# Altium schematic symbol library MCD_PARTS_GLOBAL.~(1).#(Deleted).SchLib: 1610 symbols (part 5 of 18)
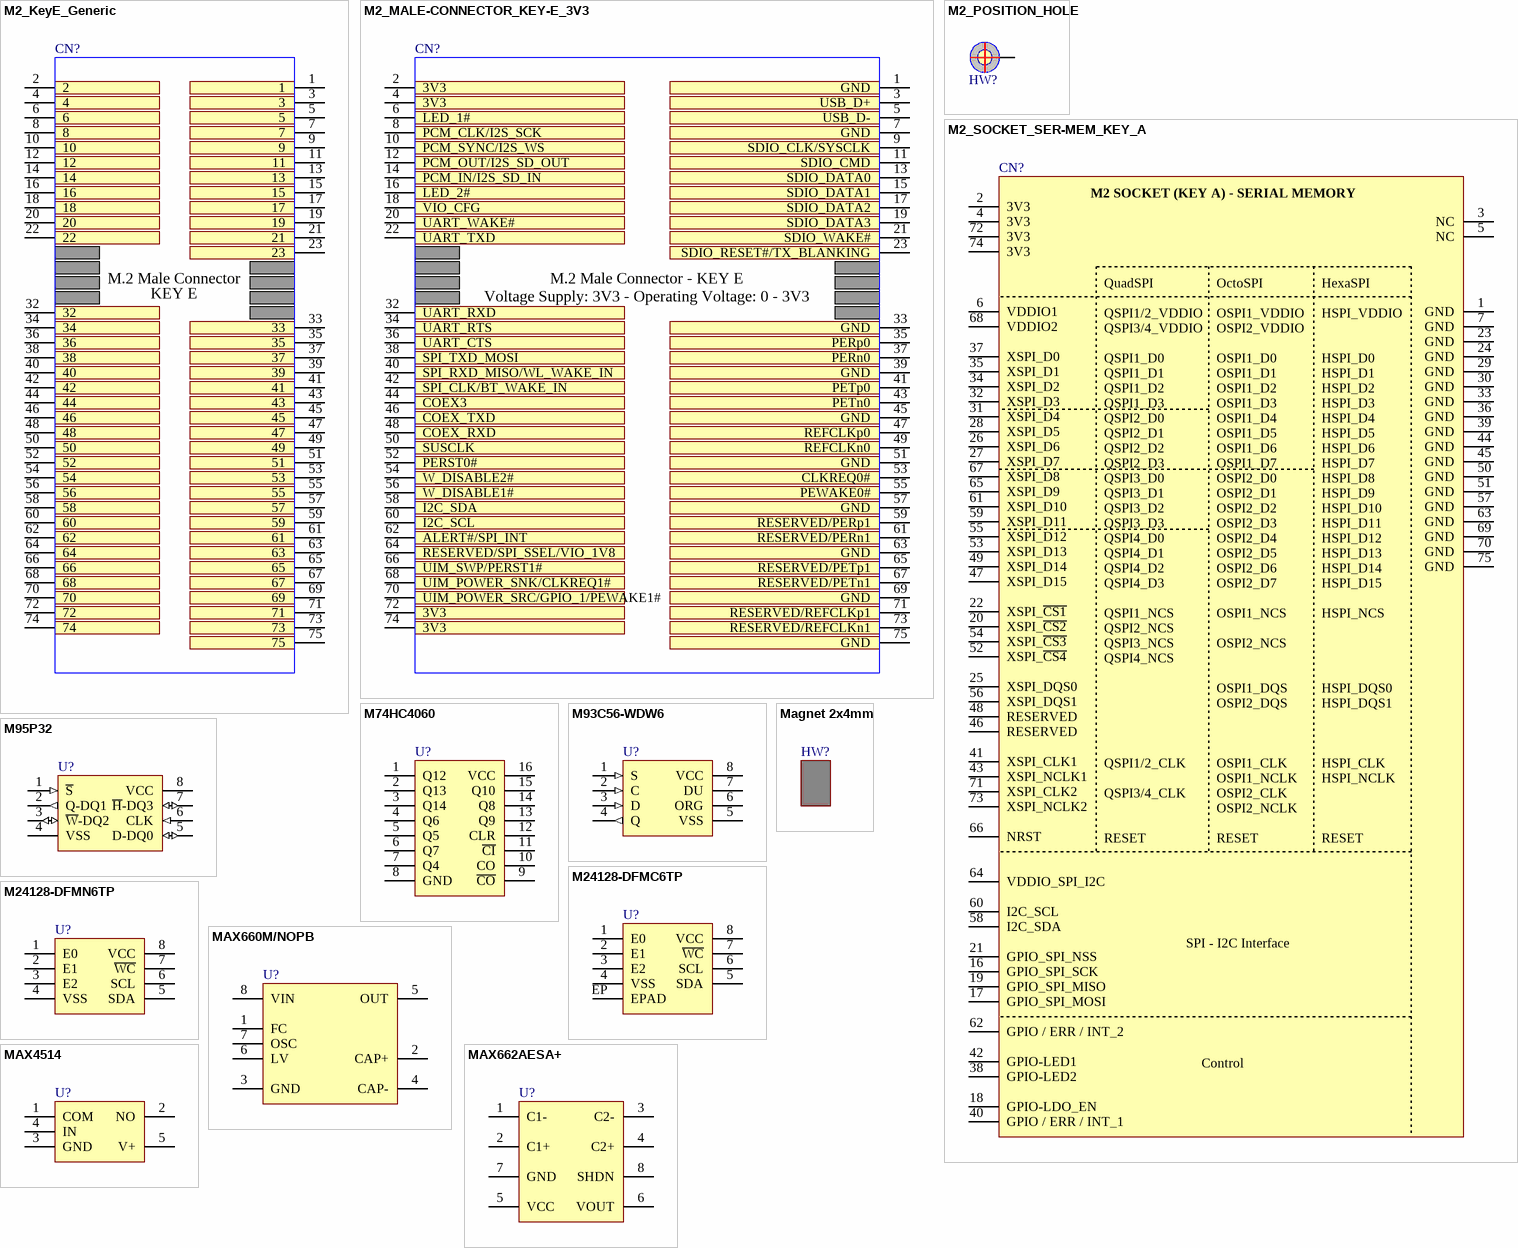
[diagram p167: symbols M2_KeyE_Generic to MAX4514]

## M2_SOCKET_SER-MEM_KEY_A
designator CN?
pins: 1 GND, 2 3V3, 3 NC, 4 3V3, 5 NC, 6 VDDIO1, 7 GND, 16 GPIO_SPI_SCK, 17 GPIO_SPI_MOSI, 18 GPIO-LDO_EN, 19 GPIO_SPI_MISO, 20 XSPI_~{CS2}, 21 GPIO_SPI_NSS, 22 XSPI_~{CS1}, 23 GND, 24 GND, 25 XSPI_DQS0, 26 XSPI_D6, 27 XSPI_D7, 28 XSPI_D5, 29 GND, 30 GND, 31 XSPI_D4, 32 XSPI_D3, 33 GND, 34 XSPI_D2, 35 XSPI_D1, 36 GND, 37 XSPI_D0, 38 GPIO-LED2, 39 GND, 40 GPIO / ERR / INT_1, 41 XSPI_CLK1, 42 GPIO-LED1, 43 XSPI_NCLK1, 44 GND, 45 GND, 46 RESERVED, 47 XSPI_D15, 48 RESERVED, 49 XSPI_D14, 50 GND, 51 GND, 52 XSPI_~{CS4}, 53 XSPI_D13, 54 XSPI_~{CS3}, 55 XSPI_D12, 56 XSPI_DQS1, 57 GND, 58 I2C_SDA, 59 XSPI_D11, 60 I2C_SCL, 61 XSPI_D10, 62 GPIO / ERR / INT_2, 63 GND, 64 VDDIO_SPI_I2C, 65 XSPI_D9, 66 NRST, 67 XSPI_D8, 68 VDDIO2, 69 GND, 70 GND, 71 XSPI_CLK2, 72 3V3, 73 XSPI_NCLK2, 74 3V3, 75 GND
1 alternate drawing of the same symbol

## M74HC4060
designator U?
pins: 1 Q12, 2 Q13, 3 Q14, 4 Q6, 5 Q5, 6 Q7, 7 Q4, 8 GND, 9 ~{CO}, 10 CO, 11 ~{CI}, 12 CLR, 13 Q9, 14 Q8, 15 Q10, 16 VCC

## M93C56-WDW6
designator U?
pins: 1 S (in), 2 C (in), 3 D (in), 4 Q (out), 5 VSS, 6 ORG, 7 DU, 8 VCC (power)

## M95P32
designator U?
pins: 1 ~{S} (in), 2 Q-DQ1 (out), 3 ~{W}-DQ2 (io), 4 VSS (power), 5 D-DQ0 (io), 6 CLK (in), 7 ~{H}-DQ3 (io), 8 VCC (power)

## M24128-DFMC6TP
designator U?
pins: 1 E0, 2 E1, 3 E2, 4 VSS, 5 SDA, 6 SCL, 7 ~{WC}, 8 VCC, EP EPAD

## M24128-DFMN6TP
designator U?
pins: 1 E0, 2 E1, 3 E2, 4 VSS, 5 SDA, 6 SCL, 7 ~{WC}, 8 VCC

## Magnet 2x4mm
designator HW?  (mechanical)

## MAX660M/NOPB
designator U?
pins: 1 FC, 2 CAP+, 3 GND, 4 CAP-, 5 OUT, 6 LV, 7 OSC, 8 VIN

## MAX662AESA+
designator U?
pins: 1 C1-, 2 C1+, 3 C2-, 4 C2+, 5 VCC, 6 VOUT, 7 GND, 8 SHDN

## MAX4514
designator U?
pins: 1 COM, 2 NO, 3 GND, 4 IN, 5 V+

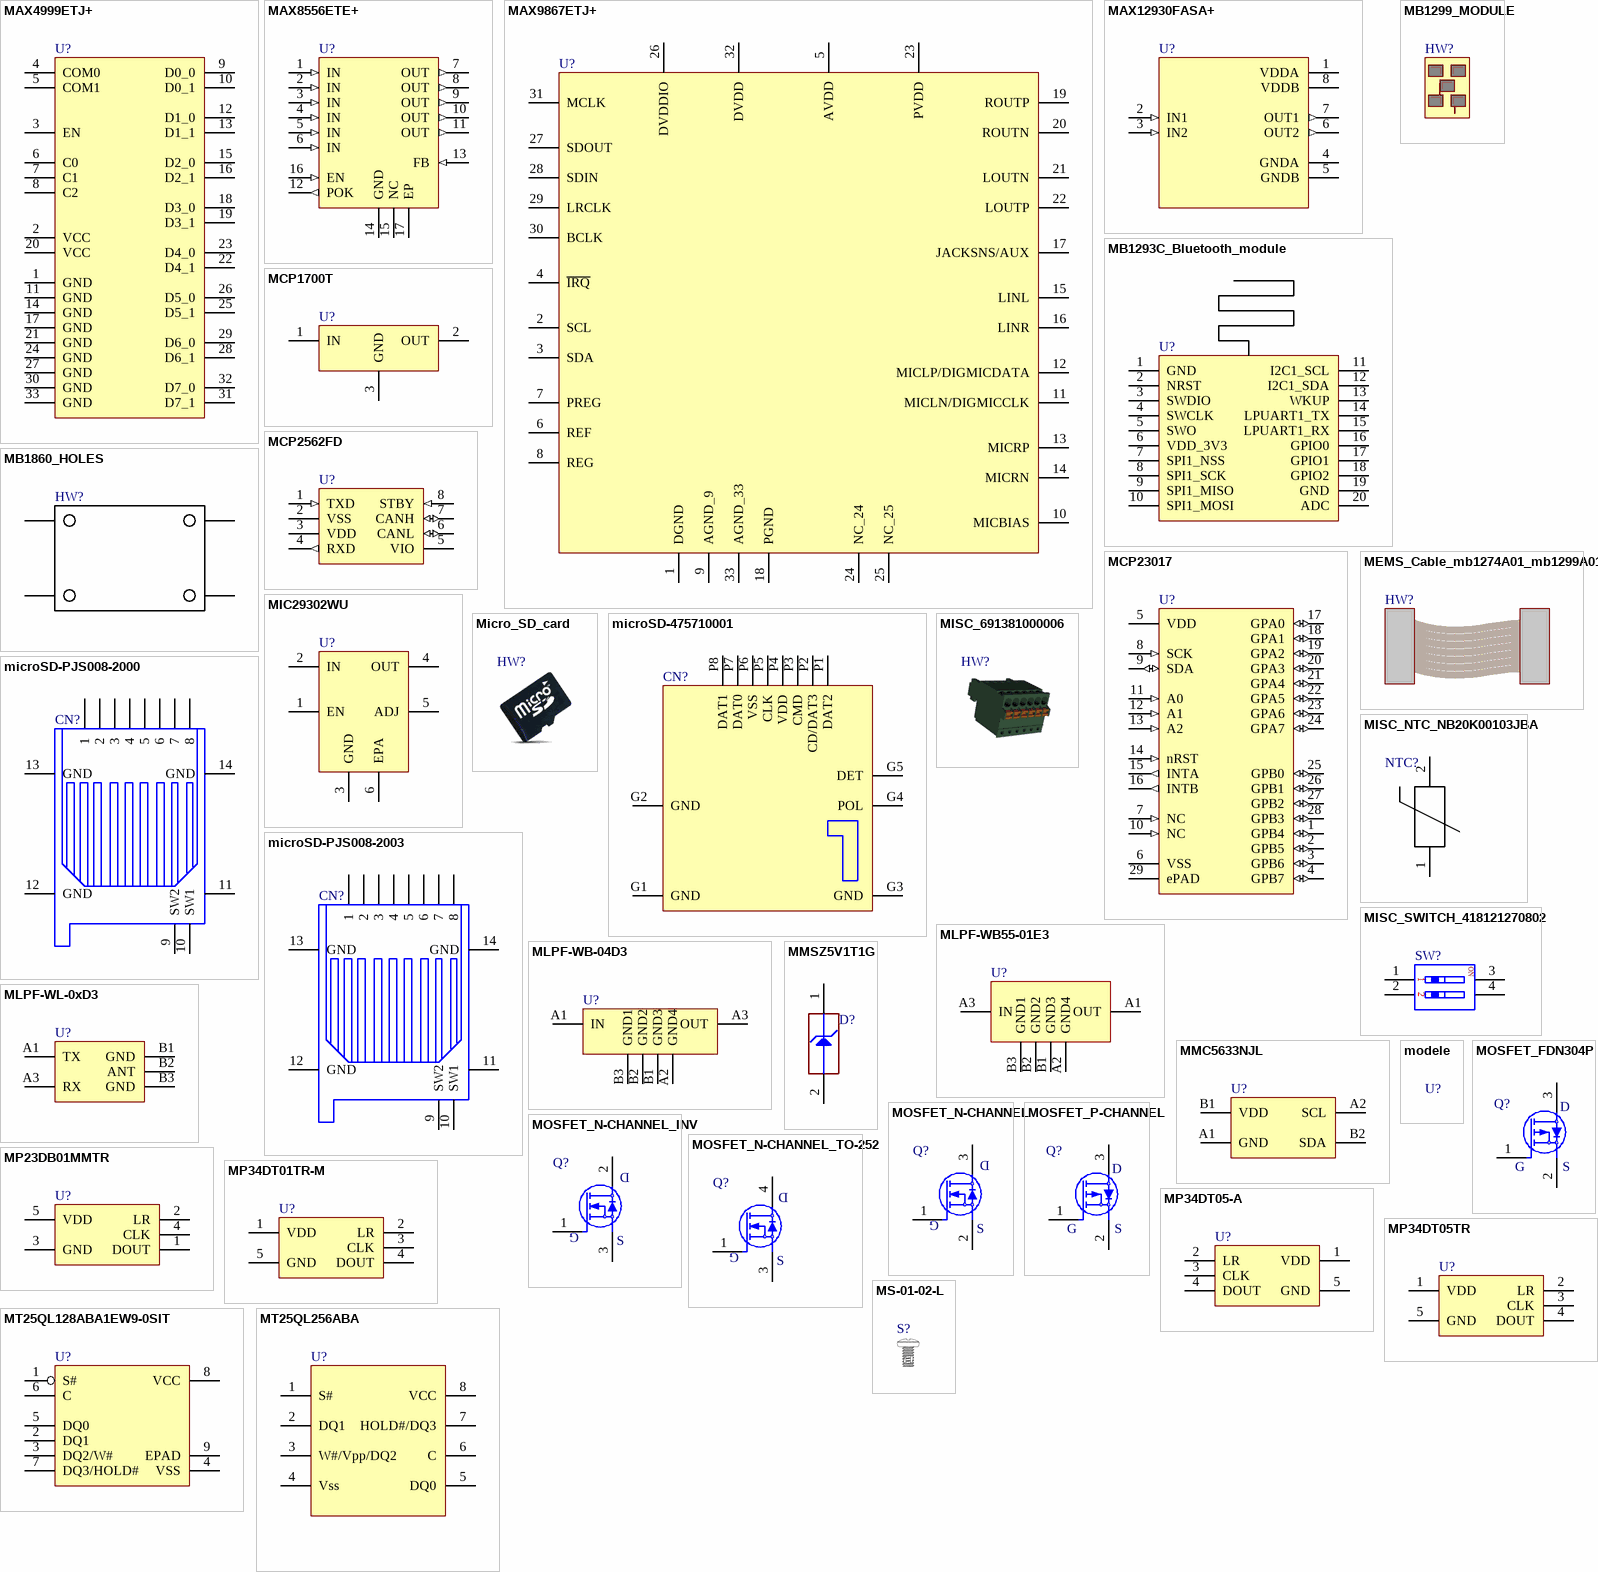
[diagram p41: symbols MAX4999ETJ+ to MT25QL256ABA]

## MAX4999ETJ+
designator U?
pins: 1 GND, 2 VCC, 3 EN, 4 COM0, 5 COM1, 6 C0, 7 C1, 8 C2, 9 D0_0, 10 D0_1, 11 GND, 12 D1_0, 13 D1_1, 14 GND, 15 D2_0, 16 D2_1, 17 GND, 18 D3_0, 19 D3_1, 20 VCC, 21 GND, 22 D4_1, 23 D4_0, 24 GND, 25 D5_1, 26 D5_0, 27 GND, 28 D6_1, 29 D6_0, 30 GND, 31 D7_1, 32 D7_0, 33 GND

## MAX8556ETE+
designator U?
pins: 1 IN (in), 2 IN (in), 3 IN (in), 4 IN (in), 5 IN (in), 6 IN (in), 7 OUT (out), 8 OUT (out), 9 OUT (out), 10 OUT (out), 11 OUT (out), 12 POK (out), 13 FB (in), 14 GND (power), 15 NC, 16 EN (in), 17 EP

## MAX9867ETJ+
designator U?
pins: 1 DGND, 2 SCL, 3 SDA, 4 ~{IRQ}, 5 AVDD, 6 REF, 7 PREG, 8 REG, 9 AGND_9, 10 MICBIAS, 11 MICLN/DIGMICCLK, 12 MICLP/DIGMICDATA, 13 MICRP, 14 MICRN, 15 LINL, 16 LINR, 17 JACKSNS/AUX, 18 PGND, 19 ROUTP, 20 ROUTN, 21 LOUTN, 22 LOUTP, 23 PVDD, 24 NC_24, 25 NC_25, 26 DVDDIO, 27 SDOUT, 28 SDIN, 29 LRCLK, 30 BCLK, 31 MCLK, 32 DVDD, 33 AGND_33

## MAX12930FASA+
designator U?
pins: 1 VDDA (power), 2 IN1 (in), 3 IN2 (in), 4 GNDA (power), 5 GNDB (power), 6 OUT2 (out), 7 OUT1 (out), 8 VDDB (power)

## MB1293C_Bluetooth_module
designator U?
pins: 1 GND, 2 NRST, 3 SWDIO, 4 SWCLK, 5 SWO, 6 VDD_3V3, 7 SPI1_NSS, 8 SPI1_SCK, 9 SPI1_MISO, 10 SPI1_MOSI, 11 I2C1_SCL, 12 I2C1_SDA, 13 WKUP, 14 LPUART1_TX, 15 LPUART1_RX, 16 GPIO0, 17 GPIO1, 18 GPIO2, 19 GND, 20 ADC

## MB1299_MODULE
designator HW?  (mechanical)

## MB1860_HOLES
designator HW?  (no BOM)
pins: GND1, GND2, GND3, GND4

## MCP1700T
designator U?
pins: 1 IN, 2 OUT, 3 GND

## MCP2562FD
designator U?
pins: 1 TXD (in), 2 VSS (power), 3 VDD (power), 4 RXD (out), 5 VIO (power), 6 CANL (io), 7 CANH (io), 8 STBY (in)

## MCP23017
designator U?
pins: 1 GPB4 (io), 2 GPB5 (io), 3 GPB6 (io), 4 GPB7 (io), 5 VDD (power), 6 VSS (power), 7 NC (in), 8 SCK (in), 9 SDA (io), 10 NC (in), 11 A0 (in), 12 A1 (in), 13 A2 (in), 14 nRST (in), 15 INTA (out), 16 INTB (out), 17 GPA0 (io), 18 GPA1 (io), 19 GPA2 (io), 20 GPA3 (io), 21 GPA4 (io), 22 GPA5 (io), 23 GPA6 (io), 24 GPA7 (io), 25 GPB0 (io), 26 GPB1 (io), 27 GPB2 (io), 28 GPB3 (io), 29 ePAD (power)

## MEMS_Cable_mb1274A01_mb1299A01
designator HW?  (mechanical)

## MIC29302WU
designator U?
pins: 1 EN, 2 IN, 3 GND, 4 OUT, 5 ADJ, 6 EPA

## Micro_SD_card
designator HW?  (mechanical)

## microSD-475710001
designator CN?
pins: G1 GND, G2 GND, G3 GND, G4 POL, G5 DET, P1 DAT2, P2 CD/DAT3, P3 CMD, P4 VDD, P5 CLK, P6 VSS, P7 DAT0, P8 DAT1

## microSD-PJS008-2000
designator CN?
pins: 1, 2, 3, 4, 5, 6, 7, 8, 9 SW2, 10 SW1, 11 GND, 12 GND, 13 GND, 14 GND

## microSD-PJS008-2003
designator CN?
pins: 1, 2, 3, 4, 5, 6, 7, 8, 9 SW2, 10 SW1, 11 GND, 12 GND, 13 GND, 14 GND
1 alternate drawing of the same symbol

## MISC_691381000006
designator HW?

## MISC_NTC_NB20K00103JBA
designator NTC?
pins: 1, 2

## MISC_SWITCH_418121270802
designator SW?
pins: 1, 2, 3, 4

## MLPF-WB55-01E3
designator U?
pins: A1 OUT, A2 GND4, A3 IN, B1 GND3, B2 GND2, B3 GND1

## MLPF-WB-04D3
designator U?
pins: A1 IN, A2 GND4, A3 OUT, B1 GND3, B2 GND2, B3 GND1

## MLPF-WL-0xD3
designator U?
pins: A1 TX, A3 RX, B1 GND, B2 ANT, B3 GND

## MMC5633NJL
designator U?
pins: A1 GND, A2 SCL, B1 VDD, B2 SDA

## MMSZ5V1T1G
designator D?
pins: 1 K, 2 A

## modele
designator U?

## MOSFET_FDN304P
designator Q?
pins: 1 G, 2 S, 3 D

## MOSFET_N-CHANNEL
designator Q?
pins: 1 G, 2 S, 3 D

## MOSFET_N-CHANNEL_INV
designator Q?
pins: 1 G, 2 D, 3 S

## MOSFET_N-CHANNEL_TO-252
designator Q?
pins: 1 G, 3 S, 4 D

## MOSFET_P-CHANNEL
designator Q?
pins: 1 G, 2 S, 3 D

## MP23DB01MMTR
designator U?
pins: 1 DOUT, 2 LR, 3 GND, 4 CLK, 5 VDD

## MP34DT01TR-M
designator U?
pins: 1 VDD, 2 LR, 3 CLK, 4 DOUT, 5 GND

## MP34DT05-A
designator U?
pins: 1 VDD, 2 LR, 3 CLK, 4 DOUT, 5 GND

## MP34DT05TR
designator U?
pins: 1 VDD, 2 LR, 3 CLK, 4 DOUT, 5 GND

## MS-01-02-L
designator S?  (mechanical)

## MT25QL128ABA1EW9-0SIT
designator U?
pins: 1 S#, 2 DQ1, 3 DQ2/W#, 4 VSS, 5 DQ0, 6 C, 7 DQ3/HOLD#, 8 VCC, 9 EPAD

## MT25QL256ABA
designator U?
pins: 1 S#, 2 DQ1, 3 W#/Vpp/DQ2, 4 Vss, 5 DQ0, 6 C, 7 HOLD#/DQ3, 8 VCC

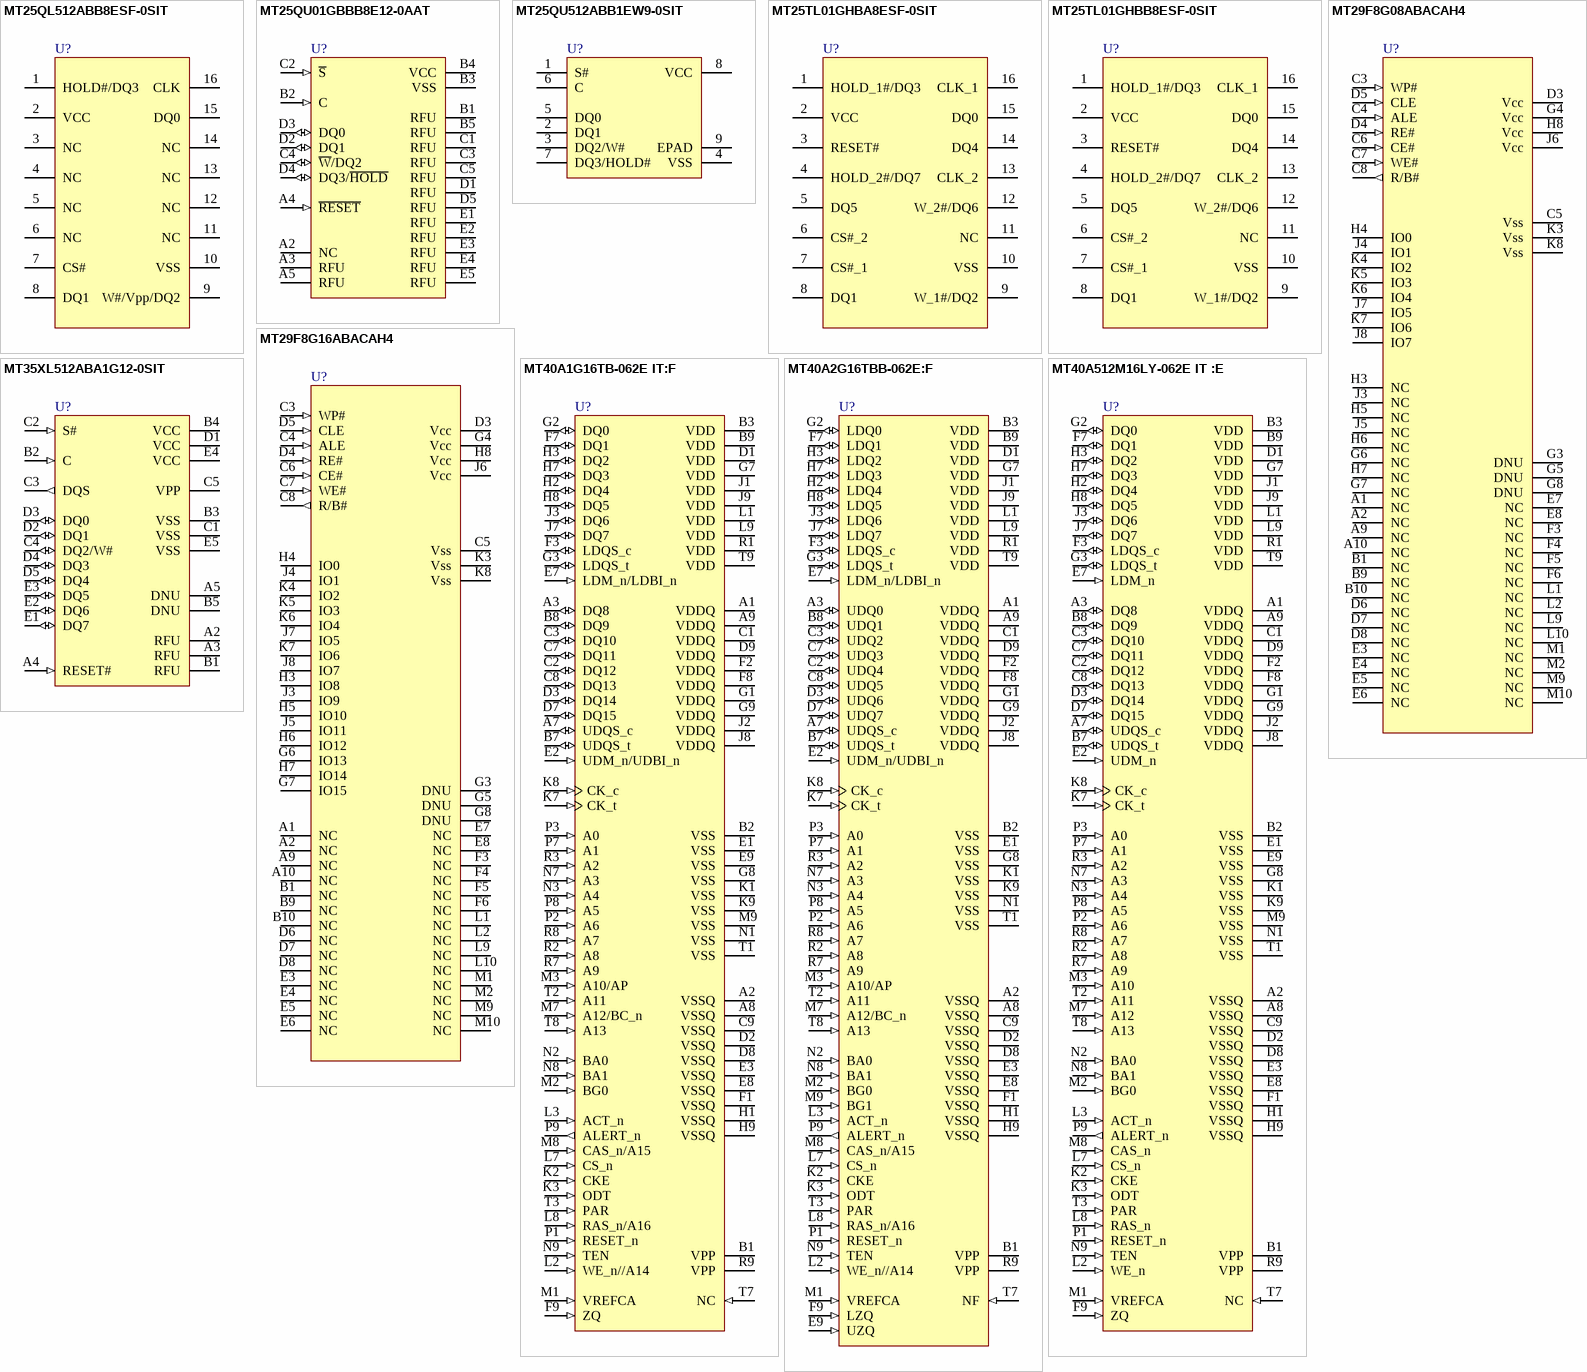
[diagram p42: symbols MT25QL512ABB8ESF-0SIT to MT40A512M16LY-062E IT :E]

## MT25QL512ABB8ESF-0SIT
designator U?
pins: 1 HOLD#/DQ3, 2 VCC, 3 NC, 4 NC, 5 NC, 6 NC, 7 CS#, 8 DQ1, 9 W#/Vpp/DQ2, 10 VSS, 11 NC, 12 NC, 13 NC, 14 NC, 15 DQ0, 16 CLK

## MT25QU01GBBB8E12-0AAT
designator U?
pins: A2 NC, A3 RFU, A4 ~{RESET} (in), A5 RFU, B1 RFU, B2 C (in), B3 VSS, B4 VCC (power), B5 RFU, C1 RFU, C2 ~{S} (in), C3 RFU, C4 ~{W}/DQ2 (io), C5 RFU, D1 RFU, D2 DQ1 (io), D3 DQ0 (io), D4 DQ3/~{HOLD} (io), D5 RFU, E1 RFU, E2 RFU, E3 RFU, E4 RFU, E5 RFU

## MT25QU512ABB1EW9-0SIT
designator U?
pins: 1 S#, 2 DQ1, 3 DQ2/W#, 4 VSS, 5 DQ0, 6 C, 7 DQ3/HOLD#, 8 VCC, 9 EPAD

## MT25TL01GHBA8ESF-0SIT
designator U?
pins: 1 HOLD_1#/DQ3, 2 VCC, 3 RESET#, 4 HOLD_2#/DQ7, 5 DQ5, 6 CS#_2, 7 CS#_1, 8 DQ1, 9 W_1#/DQ2, 10 VSS, 11 NC, 12 W_2#/DQ6, 13 CLK_2, 14 DQ4, 15 DQ0, 16 CLK_1

## MT25TL01GHBB8ESF-0SIT
designator U?
pins: 1 HOLD_1#/DQ3, 2 VCC, 3 RESET#, 4 HOLD_2#/DQ7, 5 DQ5, 6 CS#_2, 7 CS#_1, 8 DQ1, 9 W_1#/DQ2, 10 VSS, 11 NC, 12 W_2#/DQ6, 13 CLK_2, 14 DQ4, 15 DQ0, 16 CLK_1

## MT29F8G08ABACAH4
designator U?
pins: A1 NC, A2 NC, A9 NC, A10 NC, B1 NC, B9 NC, B10 NC, C3 WP# (in), C4 ALE (in), C5 Vss, C6 CE# (in), C7 WE# (in), C8 R/B# (out), D3 Vcc, D4 RE# (in), D5 CLE (in), D6 NC, D7 NC, D8 NC, E3 NC, E4 NC, E5 NC, E6 NC, E7 NC, E8 NC, F3 NC, F4 NC, F5 NC, F6 NC, G3 DNU, G4 Vcc, G5 DNU, G6 NC, G7 NC, G8 DNU, H3 NC, H4 IO0, H5 NC, H6 NC, H7 NC, H8 Vcc, J3 NC, J4 IO1, J5 NC, J6 Vcc, J7 IO5, J8 IO7, K3 Vss, K4 IO2, K5 IO3, K6 IO4, K7 IO6, K8 Vss, L1 NC, L2 NC, L9 NC, L10 NC, M1 NC, M2 NC, M9 NC, M10 NC

## MT29F8G16ABACAH4
designator U?
pins: A1 NC, A2 NC, A9 NC, A10 NC, B1 NC, B9 NC, B10 NC, C3 WP# (in), C4 ALE (in), C5 Vss, C6 CE# (in), C7 WE# (in), C8 R/B# (out), D3 Vcc, D4 RE# (in), D5 CLE (in), D6 NC, D7 NC, D8 NC, E3 NC, E4 NC, E5 NC, E6 NC, E7 NC, E8 NC, F3 NC, F4 NC, F5 NC, F6 NC, G3 DNU, G4 Vcc, G5 DNU, G6 IO13, G7 IO15, G8 DNU, H3 IO8, H4 IO0, H5 IO10, H6 IO12, H7 IO14, H8 Vcc, J3 IO9, J4 IO1, J5 IO11, J6 Vcc, J7 IO5, J8 IO7, K3 Vss, K4 IO2, K5 IO3, K6 IO4, K7 IO6, K8 Vss, L1 NC, L2 NC, L9 NC, L10 NC, M1 NC, M2 NC, M9 NC, M10 NC

## MT35XL512ABA1G12-0SIT
designator U?
pins: A2 RFU, A3 RFU, A4 RESET# (in), A5 DNU, B1 RFU, B2 C (in), B3 VSS (power), B4 VCC (power), B5 DNU, C1 VSS (power), C2 S# (in), C3 DQS (out), C4 DQ2/W# (io), C5 VPP (power), D1 VCC (power), D2 DQ1 (io), D3 DQ0 (io), D4 DQ3 (io), D5 DQ4 (io), E1 DQ7 (io), E2 DQ6 (io), E3 DQ5 (io), E4 VCC (power), E5 VSS (power)

## MT40A1G16TB-062E IT:F
designator U?
pins: A1 VDDQ (power) "DQ power supply: Isolated on the die for improved noise immunity.", A2 VSSQ (power) "DQ ground.", A3 DQ8 (io) "Data input/output: Bidirectional data bus.", A7 UDQS_c (io) "Data strobe: The data strobe is bidirectional (used for read and write data) andcomplementary (DQS and DQS#). It is edge-aligned output with read data andcentered input with write data. DQS[3:0]/DQS[3:0]# is DQS for each of (See Datasheet)", A8 VSSQ (power) "DQ ground.", A9 VDDQ (power) "DQ power supply: Isolated on the die for improved noise immunity.", B1 VPP (power) "DRAM activating power supply", B2 VSS (power) "Common ground.", B3 VDD (power) "Power supply", B7 UDQS_t (io) "Data strobe: The data strobe is bidirectional (used for read and write data) andcomplementary (DQS and DQS#). It is edge-aligned output with read data andcentered input with write data. DQS[3:0]/DQS[3:0]# is DQS for each of (See Datasheet)", B8 DQ9 (io) "Data input/output: Bidirectional data bus.", B9 VDD (power) "Power supply", C1 VDDQ (power) "DQ power supply: Isolated on the die for improved noise immunity.", C2 DQ12 (io) "Data input/output: Bidirectional data bus.", C3 DQ10 (io) "Data input/output: Bidirectional data bus.", C7 DQ11 (io) "Data input/output: Bidirectional data bus.", C8 DQ13 (io) "Data input/output: Bidirectional data bus.", C9 VSSQ (power) "DQ ground.", D1 VDD (power) "Power supply", D2 VSSQ (power) "DQ ground.", D3 DQ14 (io) "Data input/output: Bidirectional data bus.", D7 DQ15 (io) "Data input/output: Bidirectional data bus.", D8 VSSQ (power) "DQ ground.", D9 VDDQ (power) "DQ power supply: Isolated on the die for improved noise immunity.", E1 VSS (power) "Common ground.", E2 UDM_n/UDBI_n (in) "Input data mask: DM is an input mask signal for write data. Although DM ballsare input-only, the DM loading is designed to match that of DQ and DQS balls.DM[3:0] is DM for each of the four data bytes, respectively.", E3 VSSQ (power) "DQ ground.", E7 LDM_n/LDBI_n (in) "Input data mask: DM is an input mask signal for write data. Although DM ballsare input-only, the DM loading is designed to match that of DQ and DQS balls.DM[3:0] is DM for each of the four data bytes, respectively.", E8 VSSQ (power) "DQ ground.", E9 VSS (power) "Common ground.", F1 VSSQ (power) "DQ ground.", F2 VDDQ (power) "DQ power supply: Isolated on the die for improved noise immunity.", F3 LDQS_c (io) "Data strobe: The data strobe is bidirectional (used for read and write data) andcomplementary (DQS and DQS#). It is edge-aligned output with read data andcentered input with write data. DQS[3:0]/DQS[3:0]# is DQS for each of (See Datasheet)", F7 DQ1 (io) "Data input/output: Bidirectional data bus.", F8 VDDQ (power) "DQ power supply: Isolated on the die for improved noise immunity.", F9 ZQ (in) "External impedance (240 ohm): This signal is used to calibrate the device output impedance.", G1 VDDQ (power) "DQ power supply: Isolated on the die for improved noise immunity.", G2 DQ0 (io) "Data input/output: Bidirectional data bus.", G3 LDQS_t (io) "Data strobe: The data strobe is bidirectional (used for read and write data) andcomplementary (DQS and DQS#). It is edge-aligned output with read data andcentered input with write data. DQS[3:0]/DQS[3:0]# is DQS for each of (See Datasheet)", G7 VDD (power) "Power supply", G8 VSS (power) "Common ground.", G9 VDDQ (power) "DQ power supply: Isolated on the die for improved noise immunity.", H1 VSSQ (power) "DQ ground.", H2 DQ4 (io) "Data input/output: Bidirectional data bus.", H3 DQ2 (io) "Data input/output: Bidirectional data bus.", H7 DQ3 (io) "Data input/output: Bidirectional data bus.", H8 DQ5 (io) "Data input/output: Bidirectional data bus.", H9 VSSQ (power) "DQ ground.", J1 VDD (power) "Power supply", J2 VDDQ (power) "DQ power supply: Isolated on the die for improved noise immunity.", J3 DQ6 (io) "Data input/output: Bidirectional data bus.", J7 DQ7 (io) "Data input/output: Bidirectional data bus.", J8 VDDQ (power) "DQ power supply: Isolated on the die for improved noise immunity.", J9 VDD (power) "Power supply", K1 VSS (power) "Common ground.", K2 CKE (in) "Clock enable: CKE HIGH activates and CKE LOW deactivates the internal clocksignals, input buffers, and output drivers. Power-saving modes are entered andexited via CKE transitions. CKE is considered part of the command code. (See Datasheet)", K3 ODT (in) "on die termination on data, data strobe and data mask", K7 CK_t (in) "Clock: CK and CK# are differential clock inputs. All CA inputs are sampled onboth rising and falling edges of CK. CS and CKE inputs are sampled at the risingedge of CK. AC timings are referenced to clock.", K8 CK_c (in) "Clock: CK and CK# are differential clock inputs. All CA inputs are sampled onboth rising and falling edges of CK. CS and CKE inputs are sampled at the risingedge of CK. AC timings are referenced to clock.", K9 VSS (power) "Common ground.", L1 VDD (power) "Power supply", L2 WE_n//A14 (in) "Command/address inputs: Provide the command and address inputs accordingto the command truth table.", L3 ACT_n (in) "Command/address inputs: Provide the command and address inputs accordingto the command truth table.", L7 CS_n (in) "Chip select: CS# is considered part of the command code and is sampled at therising edge of CK.", L8 RAS_n/A16 (in) "Command/address inputs: Provide the command and address inputs accordingto the command truth table.", L9 VDD (power) "Power supply", M1 VREFCA (in) "Reference voltage for control, command and address pins", M2 BG0 (in) "Command/address inputs: Provide the command and address inputs accordingto the command truth table.", M3 A10/AP (in) "Command/address inputs: Provide the command and address inputs accordingto the command truth table.", M7 A12/BC_n (in) "Command/address inputs: Provide the command and address inputs accordingto the command truth table.", M8 CAS_n/A15 (in) "Command/address inputs: Provide the command and address inputs accordingto the command truth table.", M9 VSS (power) "Common ground.", N1 VSS (power) "Common ground.", N2 BA0 (in) "Command/address inputs: Provide the command and address inputs accordingto the command truth table.", N3 A4 (in) "Command/address inputs: Provide the command and address inputs accordingto the command truth table.", N7 A3 (in) "Command/address inputs: Provide the command and address inputs accordingto the command truth table.", N8 BA1 (in) "Command/address inputs: Provide the command and address inputs accordingto the command truth table.", N9 TEN (in) "Connectivity test mode", P1 RESET_n (in) "Reset active low", P2 A6 (in) "Command/address inputs: Provide the command and address inputs accordingto the command truth table.", P3 A0 (in) "Command/address inputs: Provide the command and address inputs accordingto the command truth table.", P7 A1 (in) "Command/address inputs: Provide the command and address inputs accordingto the command truth table.", P8 A5 (in) "Command/address inputs: Provide the command and address inputs accordingto the command truth table.", P9 ALERT_n (out) "Alert the controller that a specific even has occurred", R1 VDD (power) "Power supply", R2 A8 (in) "Command/address inputs: Provide the command and address inputs accordingto the command truth table.", R3 A2 (in) "Command/address inputs: Provide the command and address inputs accordingto the command truth table.", R7 A9 (in) "Command/address inputs: Provide the command and address inputs accordingto the command truth table.", R8 A7 (in) "Command/address inputs: Provide the command and address inputs accordingto the command truth table.", R9 VPP (power) "DRAM activating power supply", T1 VSS (power) "Common ground.", T2 A11 (in) "Command/address inputs: Provide the command and address inputs accordingto the command truth table.", T3 PAR (in) "Parity for command and address", T7 NC (in) "Not connected", T8 A13 (in) "Command/address inputs: Provide the command and address inputs accordingto the command truth table.", T9 VDD (power) "Power supply"

## MT40A2G16TBB-062E:F
designator U?
pins: A1 VDDQ (power) "DQ power supply: Isolated on the die for improved noise immunity.", A2 VSSQ (power) "DQ ground.", A3 UDQ0 (io) "Data input/output: Bidirectional data bus.", A7 UDQS_c (io) "Data strobe: The data strobe is bidirectional (used for read and write data) andcomplementary (DQS and DQS#). It is edge-aligned output with read data andcentered input with write data. DQS[3:0]/DQS[3:0]# is DQS for each of (See Datasheet)", A8 VSSQ (power) "DQ ground.", A9 VDDQ (power) "DQ power supply: Isolated on the die for improved noise immunity.", B1 VPP (power) "DRAM activating power supply", B2 VSS (power) "Common ground.", B3 VDD (power) "Power supply", B7 UDQS_t (io) "Data strobe: The data strobe is bidirectional (used for read and write data) andcomplementary (DQS and DQS#). It is edge-aligned output with read data andcentered input with write data. DQS[3:0]/DQS[3:0]# is DQS for each of (See Datasheet)", B8 UDQ1 (io) "Data input/output: Bidirectional data bus.", B9 VDD (power) "Power supply", C1 VDDQ (power) "DQ power supply: Isolated on the die for improved noise immunity.", C2 UDQ4 (io) "Data input/output: Bidirectional data bus.", C3 UDQ2 (io) "Data input/output: Bidirectional data bus.", C7 UDQ3 (io) "Data input/output: Bidirectional data bus.", C8 UDQ5 (io) "Data input/output: Bidirectional data bus.", C9 VSSQ (power) "DQ ground.", D1 VDD (power) "Power supply", D2 VSSQ (power) "DQ ground.", D3 UDQ6 (io) "Data input/output: Bidirectional data bus.", D7 UDQ7 (io) "Data input/output: Bidirectional data bus.", D8 VSSQ (power) "DQ ground.", D9 VDDQ (power) "DQ power supply: Isolated on the die for improved noise immunity.", E1 VSS (power) "Common ground.", E2 UDM_n/UDBI_n (in) "Input data mask: DM is an input mask signal for write data. Although DM ballsare input-only, the DM loading is designed to match that of DQ and DQS balls.DM[3:0] is DM for each of the four data bytes, respectively.", E3 VSSQ (power) "DQ ground.", E7 LDM_n/LDBI_n (in) "Input data mask: DM is an input mask signal for write data. Although DM ballsare input-only, the DM loading is designed to match that of DQ and DQS balls.DM[3:0] is DM for each of the four data bytes, respectively.", E8 VSSQ (power) "DQ ground.", E9 UZQ (in) "Common ground.", F1 VSSQ (power) "DQ ground.", F2 VDDQ (power) "DQ power supply: Isolated on the die for improved noise immunity.", F3 LDQS_c (io) "Data strobe: The data strobe is bidirectional (used for read and write data) andcomplementary (DQS and DQS#). It is edge-aligned output with read data andcentered input with write data. DQS[3:0]/DQS[3:0]# is DQS for each of (See Datasheet)", F7 LDQ1 (io) "Data input/output: Bidirectional data bus.", F8 VDDQ (power) "DQ power supply: Isolated on the die for improved noise immunity.", F9 LZQ (in) "External impedance (240 ohm): This signal is used to calibrate the device output impedance.", G1 VDDQ (power) "DQ power supply: Isolated on the die for improved noise immunity.", G2 LDQ0 (io) "Data input/output: Bidirectional data bus.", G3 LDQS_t (io) "Data strobe: The data strobe is bidirectional (used for read and write data) andcomplementary (DQS and DQS#). It is edge-aligned output with read data andcentered input with write data. DQS[3:0]/DQS[3:0]# is DQS for each of (See Datasheet)", G7 VDD (power) "Power supply", G8 VSS (power) "Common ground.", G9 VDDQ (power) "DQ power supply: Isolated on the die for improved noise immunity.", H1 VSSQ (power) "DQ ground.", H2 LDQ4 (io) "Data input/output: Bidirectional data bus.", H3 LDQ2 (io) "Data input/output: Bidirectional data bus.", H7 LDQ3 (io) "Data input/output: Bidirectional data bus.", H8 LDQ5 (io) "Data input/output: Bidirectional data bus.", H9 VSSQ (power) "DQ ground.", J1 VDD (power) "Power supply", J2 VDDQ (power) "DQ power supply: Isolated on the die for improved noise immunity.", J3 LDQ6 (io) "Data input/output: Bidirectional data bus.", J7 LDQ7 (io) "Data input/output: Bidirectional data bus.", J8 VDDQ (power) "DQ power supply: Isolated on the die for improved noise immunity.", J9 VDD (power) "Power supply", K1 VSS (power) "Common ground.", K2 CKE (in) "Clock enable: CKE HIGH activates and CKE LOW deactivates the internal clocksignals, input buffers, and output drivers. Power-saving modes are entered andexited via CKE transitions. CKE is considered part of the command code. (See Datasheet)", K3 ODT (in) "on die termination on data, data strobe and data mask", K7 CK_t (in) "Clock: CK and CK# are differential clock inputs. All CA inputs are sampled onboth rising and falling edges of CK. CS and CKE inputs are sampled at the risingedge of CK. AC timings are referenced to clock.", K8 CK_c (in) "Clock: CK and CK# are differential clock inputs. All CA inputs are sampled onboth rising and falling edges of CK. CS and CKE inputs are sampled at the risingedge of CK. AC timings are referenced to clock.", K9 VSS (power) "Common ground.", L1 VDD (power) "Power supply", L2 WE_n//A14 (in) "Command/address inputs: Provide the command and address inputs accordingto the command truth table.", L3 ACT_n (in) "Command/address inputs: Provide the command and address inputs accordingto the command truth table.", L7 CS_n (in) "Chip select: CS# is considered part of the command code and is sampled at therising edge of CK.", L8 RAS_n/A16 (in) "Command/address inputs: Provide the command and address inputs accordingto the command truth table.", L9 VDD (power) "Power supply", M1 VREFCA (in) "Reference voltage for control, command and address pins", M2 BG0 (in) "Command/address inputs: Provide the command and address inputs accordingto the command truth table.", M3 A10/AP (in) "Command/address inputs: Provide the command and address inputs accordingto the command truth table.", M7 A12/BC_n (in) "Command/address inputs: Provide the command and address inputs accordingto the command truth table.", M8 CAS_n/A15 (in) "Command/address inputs: Provide the command and address inputs accordingto the command truth table.", M9 BG1 (in) "Common ground.", N1 VSS (power) "Common ground.", N2 BA0 (in) "Command/address inputs: Provide the command and address inputs accordingto the command truth table.", N3 A4 (in) "Command/address inputs: Provide the command and address inputs accordingto the command truth table.", N7 A3 (in) "Command/address inputs: Provide the command and address inputs accordingto the command truth table.", N8 BA1 (in) "Command/address inputs: Provide the command and address inputs accordingto the command truth table.", N9 TEN (in) "Connectivity test mode", P1 RESET_n (in) "Reset active low", P2 A6 (in) "Command/address inputs: Provide the command and address inputs accordingto the command truth table.", P3 A0 (in) "Command/address inputs: Provide the command and address inputs accordingto the command truth table.", P7 A1 (in) "Command/address inputs: Provide the command and address inputs accordingto the command truth table.", P8 A5 (in) "Command/address inputs: Provide the command and address inputs accordingto the command truth table.", P9 ALERT_n (out) "Alert the controller that a specific even has occurred", R1 VDD (power) "Power supply", R2 A8 (in) "Command/address inputs: Provide the command and address inputs accordingto the command truth table.", R3 A2 (in) "Command/address inputs: Provide the command and address inputs accordingto the command truth table.", R7 A9 (in) "Command/address inputs: Provide the command and address inputs accordingto the command truth table.", R8 A7 (in) "Command/address inputs: Provide the command and address inputs accordingto the command truth table.", R9 VPP (power) "DRAM activating power supply", T1 VSS (power) "Common ground.", T2 A11 (in) "Command/address inputs: Provide the command and address inputs accordingto the command truth table.", T3 PAR (in) "Parity for command and address", T7 NF (in) "Not connected", T8 A13 (in) "Command/address inputs: Provide the command and address inputs accordingto the command truth table.", T9 VDD (power) "Power supply"

## MT40A512M16LY-062E IT :E
designator U?
pins: A1 VDDQ (power) "DQ power supply: Isolated on the die for improved noise immunity.", A2 VSSQ (power) "DQ ground.", A3 DQ8 (io) "Data input/output: Bidirectional data bus.", A7 UDQS_c (io) "Data strobe: The data strobe is bidirectional (used for read and write data) andcomplementary (DQS and DQS#). It is edge-aligned output with read data andcentered input with write data. DQS[3:0]/DQS[3:0]# is DQS for each of (See Datasheet)", A8 VSSQ (power) "DQ ground.", A9 VDDQ (power) "DQ power supply: Isolated on the die for improved noise immunity.", B1 VPP (power) "DRAM activating power supply", B2 VSS (power) "Common ground.", B3 VDD (power) "Power supply", B7 UDQS_t (io) "Data strobe: The data strobe is bidirectional (used for read and write data) andcomplementary (DQS and DQS#). It is edge-aligned output with read data andcentered input with write data. DQS[3:0]/DQS[3:0]# is DQS for each of (See Datasheet)", B8 DQ9 (io) "Data input/output: Bidirectional data bus.", B9 VDD (power) "Power supply", C1 VDDQ (power) "DQ power supply: Isolated on the die for improved noise immunity.", C2 DQ12 (io) "Data input/output: Bidirectional data bus.", C3 DQ10 (io) "Data input/output: Bidirectional data bus.", C7 DQ11 (io) "Data input/output: Bidirectional data bus.", C8 DQ13 (io) "Data input/output: Bidirectional data bus.", C9 VSSQ (power) "DQ ground.", D1 VDD (power) "Power supply", D2 VSSQ (power) "DQ ground.", D3 DQ14 (io) "Data input/output: Bidirectional data bus.", D7 DQ15 (io) "Data input/output: Bidirectional data bus.", D8 VSSQ (power) "DQ ground.", D9 VDDQ (power) "DQ power supply: Isolated on the die for improved noise immunity.", E1 VSS (power) "Common ground.", E2 UDM_n (in) "Input data mask: DM is an input mask signal for write data. Although DM ballsare input-only, the DM loading is designed to match that of DQ and DQS balls.DM[3:0] is DM for each of the four data bytes, respectively.", E3 VSSQ (power) "DQ ground.", E7 LDM_n (in) "Input data mask: DM is an input mask signal for write data. Although DM ballsare input-only, the DM loading is designed to match that of DQ and DQS balls.DM[3:0] is DM for each of the four data bytes, respectively.", E8 VSSQ (power) "DQ ground.", E9 VSS (power) "Common ground.", F1 VSSQ (power) "DQ ground.", F2 VDDQ (power) "DQ power supply: Isolated on the die for improved noise immunity.", F3 LDQS_c (io) "Data strobe: The data strobe is bidirectional (used for read and write data) andcomplementary (DQS and DQS#). It is edge-aligned output with read data andcentered input with write data. DQS[3:0]/DQS[3:0]# is DQS for each of (See Datasheet)", F7 DQ1 (io) "Data input/output: Bidirectional data bus.", F8 VDDQ (power) "DQ power supply: Isolated on the die for improved noise immunity.", F9 ZQ (in) "External impedance (240 ohm): This signal is used to calibrate the device output impedance.", G1 VDDQ (power) "DQ power supply: Isolated on the die for improved noise immunity.", G2 DQ0 (io) "Data input/output: Bidirectional data bus.", G3 LDQS_t (io) "Data strobe: The data strobe is bidirectional (used for read and write data) andcomplementary (DQS and DQS#). It is edge-aligned output with read data andcentered input with write data. DQS[3:0]/DQS[3:0]# is DQS for each of (See Datasheet)", G7 VDD (power) "Power supply", G8 VSS (power) "Common ground.", G9 VDDQ (power) "DQ power supply: Isolated on the die for improved noise immunity.", H1 VSSQ (power) "DQ ground.", H2 DQ4 (io) "Data input/output: Bidirectional data bus.", H3 DQ2 (io) "Data input/output: Bidirectional data bus.", H7 DQ3 (io) "Data input/output: Bidirectional data bus.", H8 DQ5 (io) "Data input/output: Bidirectional data bus.", H9 VSSQ (power) "DQ ground.", J1 VDD (power) "Power supply", J2 VDDQ (power) "DQ power supply: Isolated on the die for improved noise immunity.", J3 DQ6 (io) "Data input/output: Bidirectional data bus.", J7 DQ7 (io) "Data input/output: Bidirectional data bus.", J8 VDDQ (power) "DQ power supply: Isolated on the die for improved noise immunity.", J9 VDD (power) "Power supply", K1 VSS (power) "Common ground.", K2 CKE (in) "Clock enable: CKE HIGH activates and CKE LOW deactivates the internal clocksignals, input buffers, and output drivers. Power-saving modes are entered andexited via CKE transitions. CKE is considered part of the command code. (See Datasheet)", K3 ODT (in) "on die termination on data, data strobe and data mask", K7 CK_t (in) "Clock: CK and CK# are differential clock inputs. All CA inputs are sampled onboth rising and falling edges of CK. CS and CKE inputs are sampled at the risingedge of CK. AC timings are referenced to clock.", K8 CK_c (in) "Clock: CK and CK# are differential clock inputs. All CA inputs are sampled onboth rising and falling edges of CK. CS and CKE inputs are sampled at the risingedge of CK. AC timings are referenced to clock.", K9 VSS (power) "Common ground.", L1 VDD (power) "Power supply", L2 WE_n (in) "Command/address inputs: Provide the command and address inputs accordingto the command truth table.", L3 ACT_n (in) "Command/address inputs: Provide the command and address inputs accordingto the command truth table.", L7 CS_n (in) "Chip select: CS# is considered part of the command code and is sampled at therising edge of CK.", L8 RAS_n (in) "Command/address inputs: Provide the command and address inputs accordingto the command truth table.", L9 VDD (power) "Power supply", M1 VREFCA (in) "Reference voltage for control, command and address pins", M2 BG0 (in) "Command/address inputs: Provide the command and address inputs accordingto the command truth table.", M3 A10 (in) "Command/address inputs: Provide the command and address inputs accordingto the command truth table.", M7 A12 (in) "Command/address inputs: Provide the command and address inputs accordingto the command truth table.", M8 CAS_n (in) "Command/address inputs: Provide the command and address inputs accordingto the command truth table.", M9 VSS (power) "Common ground.", N1 VSS (power) "Common ground.", N2 BA0 (in) "Command/address inputs: Provide the command and address inputs accordingto the command truth table.", N3 A4 (in) "Command/address inputs: Provide the command and address inputs accordingto the command truth table.", N7 A3 (in) "Command/address inputs: Provide the command and address inputs accordingto the command truth table.", N8 BA1 (in) "Command/address inputs: Provide the command and address inputs accordingto the command truth table.", N9 TEN (in) "Connectivity test mode", P1 RESET_n (in) "Reset active low", P2 A6 (in) "Command/address inputs: Provide the command and address inputs accordingto the command truth table.", P3 A0 (in) "Command/address inputs: Provide the command and address inputs accordingto the command truth table.", P7 A1 (in) "Command/address inputs: Provide the command and address inputs accordingto the command truth table.", P8 A5 (in) "Command/address inputs: Provide the command and address inputs accordingto the command truth table.", P9 ALERT_n (out) "Alert the controller that a specific even has occurred", R1 VDD (power) "Power supply", R2 A8 (in) "Command/address inputs: Provide the command and address inputs accordingto the command truth table.", R3 A2 (in) "Command/address inputs: Provide the command and address inputs accordingto the command truth table.", R7 A9 (in) "Command/address inputs: Provide the command and address inputs accordingto the command truth table.", R8 A7 (in) "Command/address inputs: Provide the command and address inputs accordingto the command truth table.", R9 VPP (power) "DRAM activating power supply", T1 VSS (power) "Common ground.", T2 A11 (in) "Command/address inputs: Provide the command and address inputs accordingto the command truth table.", T3 PAR (in) "Parity for command and address", T7 NC (in) "Not connected", T8 A13 (in) "Command/address inputs: Provide the command and address inputs accordingto the command truth table.", T9 VDD (power) "Power supply"

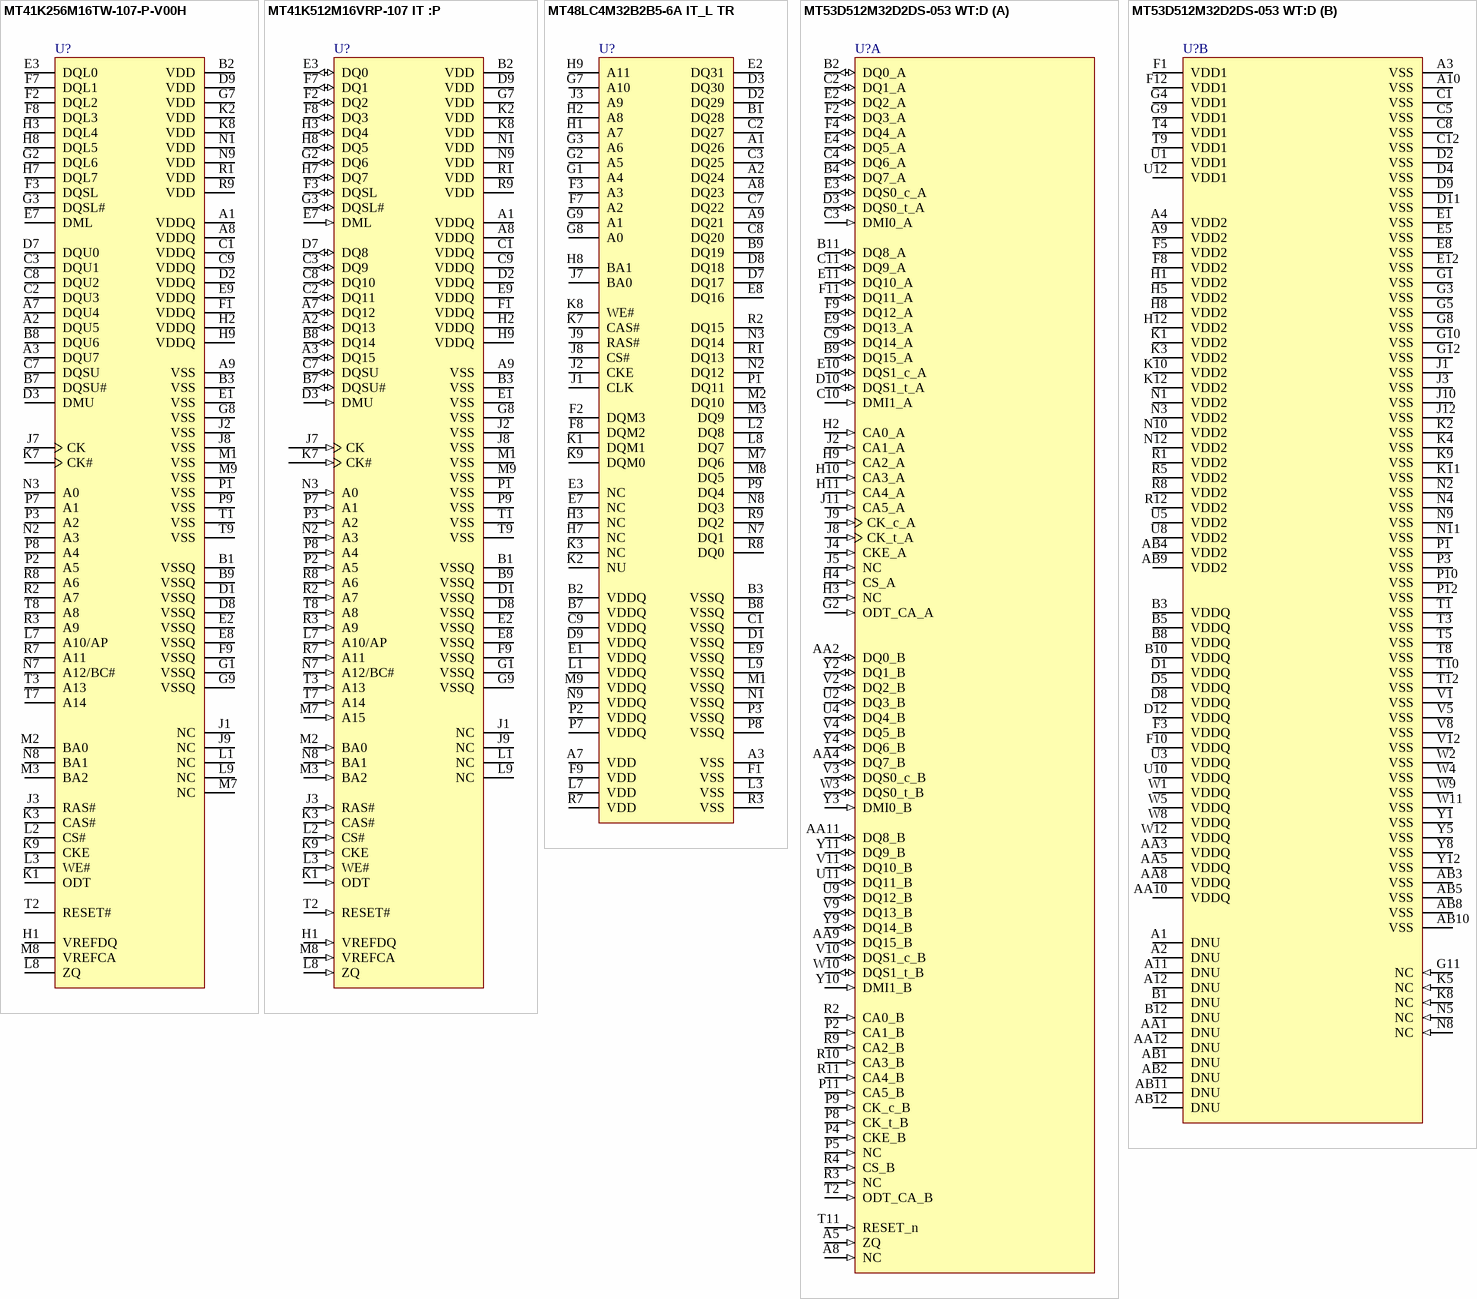
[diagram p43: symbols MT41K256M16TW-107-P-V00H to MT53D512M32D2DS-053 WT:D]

## MT41K256M16TW-107-P-V00H
designator U?
pins: A1 VDDQ "DQ Power Supply: 1.5 V +/- 0.075 V for standard voltage or 1.35V +0.1V, -0.067V for low voltage", A2 DQU5 "Data Input/ Output: Bi-directional data bus.", A3 DQU7 "Data Input/ Output: Bi-directional data bus.", A7 DQU4 "Data Input/ Output: Bi-directional data bus.", A8 VDDQ "DQ Power Supply: 1.5 V +/- 0.075 V for standard voltage or 1.35V +0.1V, -0.067V for low voltage", A9 VSS "Ground", B1 VSSQ "DQ Ground", B2 VDD "Power Supply: 1.5 V +/- 0.075 V for standard voltage or 1.35V +0.1V, -0.067V for low voltage", B3 VSS "Ground", B7 DQSU# "Data Strobe: output with read data, input with write data. Edge-aligned with read data, centered in write data. For the x16, DQSL corresponds to the data on DQL0-DQL7; DQSU corresponds to the data on DQU0-DQU7. The data strobes DQS, DQSL, and DQSU are pa", B8 DQU6 "Data Input/ Output: Bi-directional data bus.", B9 VSSQ "DQ Ground", C1 VDDQ "DQ Power Supply: 1.5 V +/- 0.075 V for standard voltage or 1.35V +0.1V, -0.067V for low voltage", C2 DQU3 "Data Input/ Output: Bi-directional data bus.", C3 DQU1 "Data Input/ Output: Bi-directional data bus.", C7 DQSU "Data Strobe: output with read data, input with write data. Edge-aligned with read data, centered in write data. For the x16, DQSL corresponds to the data on DQL0-DQL7; DQSU corresponds to the data on DQU0-DQU7. The data strobes DQS, DQSL, and DQSU are pa", C8 DQU2 "Data Input/ Output: Bi-directional data bus.", C9 VDDQ "DQ Power Supply: 1.5 V +/- 0.075 V for standard voltage or 1.35V +0.1V, -0.067V for low voltage", D1 VSSQ "DQ Ground", D2 VDDQ "DQ Power Supply: 1.5 V +/- 0.075 V for standard voltage or 1.35V +0.1V, -0.067V for low voltage", D3 DMU "Input Data Mask: DM is an input mask signal for write data. Input data is masked when DM is sampled HIGH coincident with that input data during a Write access. DM is sampled on both edges of DQS. For x8 device, the function of DM or TDQS/TDQS# is enabled", D7 DQU0 "Data Input/ Output: Bi-directional data bus.", D8 VSSQ "DQ Ground", D9 VDD "Power Supply: 1.5 V +/- 0.075 V for standard voltage or 1.35V +0.1V, -0.067V for low voltage", E1 VSS "Ground", E2 VSSQ "DQ Ground", E3 DQL0 "Data Input/ Output: Bi-directional data bus.", E7 DML "Input Data Mask: DM is an input mask signal for write data. Input data is masked when DM is sampled HIGH coincident with that input data during a Write access. DM is sampled on both edges of DQS. For x8 device, the function of DM or TDQS/TDQS# is enabled", E8 VSSQ "DQ Ground", E9 VDDQ "DQ Power Supply: 1.5 V +/- 0.075 V for standard voltage or 1.35V +0.1V, -0.067V for low voltage", F1 VDDQ "DQ Power Supply: 1.5 V +/- 0.075 V for standard voltage or 1.35V +0.1V, -0.067V for low voltage", F2 DQL2 "Data Input/ Output: Bi-directional data bus.", F3 DQSL "Data Strobe: output with read data, input with write data. Edge-aligned with read data, centered in write data. For the x16, DQSL corresponds to the data on DQL0-DQL7; DQSU corresponds to the data on DQU0-DQU7. The data strobes DQS, DQSL, and DQSU are pa", F7 DQL1 "Data Input/ Output: Bi-directional data bus.", F8 DQL3 "Data Input/ Output: Bi-directional data bus.", F9 VSSQ "DQ Ground", G1 VSSQ "DQ Ground", G2 DQL6 "Data Input/ Output: Bi-directional data bus.", G3 DQSL# "Data Strobe: output with read data, input with write data. Edge-aligned with read data, centered in write data. For the x16, DQSL corresponds to the data on DQL0-DQL7; DQSU corresponds to the data on DQU0-DQU7. The data strobes DQS, DQSL, and DQSU are pa", G7 VDD "Power Supply: 1.5 V +/- 0.075 V for standard voltage or 1.35V +0.1V, -0.067V for low voltage", G8 VSS "Ground", G9 VSSQ "DQ Ground", H1 VREFDQ "Reference voltage for DQ", H2 VDDQ "DQ Power Supply: 1.5 V +/- 0.075 V for standard voltage or 1.35V +0.1V, -0.067V for low voltage", H3 DQL4 "Data Input/ Output: Bi-directional data bus.", H7 DQL7 "Data Input/ Output: Bi-directional data bus.", H8 DQL5 "Data Input/ Output: Bi-directional data bus.", H9 VDDQ "DQ Power Supply: 1.5 V +/- 0.075 V for standard voltage or 1.35V +0.1V, -0.067V for low voltage", J1 NC "No Connect: No internal electrical connection is present.", J2 VSS "Ground", J3 RAS# "Command Inputs: RAS#, CAS# and WE# (along with CS#) define the command being entered.", J7 CK "Clock: CK and CK# are differential clock inputs. All address and control input signals are sampled on the crossing of the positive edge of CK and negative edge of CK#.", J8 VSS "Ground", J9 NC "No Connect: No internal electrical connection is present.", K1 ODT "On Die Termination: ODT (registered HIGH) enables termination resistance internal to the DDR3 SDRAM. When enabled, ODT is only applied to each DQ, DQSU, DQSU#, DQSL, DQSL#, DMU, and DML signal. The ODT pin will be ignored if MR1 and MR2 are programmed to", K2 VDD "Power Supply: 1.5 V +/- 0.075 V for standard voltage or 1.35V +0.1V, -0.067V for low voltage", K3 CAS# "Command Inputs: RAS#, CAS# and WE# (along with CS#) define the command being entered.", K7 CK# "Clock: CK and CK# are differential clock inputs. All address and control input signals are sampled on the crossing of the positive edge of CK and negative edge of CK#.", K8 VDD "Power Supply: 1.5 V +/- 0.075 V for standard voltage or 1.35V +0.1V, -0.067V for low voltage", K9 CKE "Clock Enable: CKE HIGH activates, and CKE Low deactivates, internal clock signals and device input buffers and output drivers. Taking CKE Low provides Precharge Power-Down and Self-Refresh operation (all banks idle), or Active Power-Down (row Active in a", L1 NC "No Connect: No internal electrical connection is present.", L2 CS# "Chip Select: All commands are masked when CS# is registered HIGH. CS# provides for external Rank selection on systems with multiple Ranks. CS# is considered part of the command code.", L3 WE# "Command Inputs: RAS#, CAS# and WE# (along with CS#) define the command being entered.", L7 A10/AP "Auto-precharge: A10 is sampled during Read/Write commands to determine whether Autoprecharge should be performed to the accessed bank after the Read/Write operation. (HIGH: Autoprecharge; LOW: no Autoprecharge). A10 is sampled during a Precharge command", L8 ZQ "Reference Pin for ZQ", L9 NC "No Connect: No internal electrical connection is present.", M1 VSS "Ground", M2 BA0 "Bank Address Inputs: BA0 - BA2 define to which bank an Active, Read, Write, or Precharge command is being applied. Bank address also determines which mode register is to be accessed during a MRS cycle.", M3 BA2 "Bank Address Inputs: BA0 - BA2 define to which bank an Active, Read, Write, or Precharge command is being applied. Bank address also determines which mode register is to be accessed during a MRS cycle.", M7 NC "No Connect: No internal electrical connection is present.", M8 VREFCA "Reference voltage for CA", M9 VSS "Ground", N1 VDD "Power Supply: 1.5 V +/- 0.075 V for standard voltage or 1.35V +0.1V, -0.067V for low voltage", N2 A3 "Address Inputs: Provide the row address for Active commands and the column address for Read/ Write commands to select one location out of the memory array in the respective bank. (A10/AP and A12/BC# have additional functions; see below). The address inpu", N3 A0 "Address Inputs: Provide the row address for Active commands and the column address for Read/ Write commands to select one location out of the memory array in the respective bank. (A10/AP and A12/BC# have additional functions; see below). The address inpu", N7 A12/BC# "Burst Chop: A12 / BC# is sampled during Read and Write commands to determine if burst chop (on-the-fly) will be performed. (HIGH, no burst chop; LOW: burst chopped). See command truth table for details.", N8 BA1 "Bank Address Inputs: BA0 - BA2 define to which bank an Active, Read, Write, or Precharge command is being applied. Bank address also determines which mode register is to be accessed during a MRS cycle.", N9 VDD "Power Supply: 1.5 V +/- 0.075 V for standard voltage or 1.35V +0.1V, -0.067V for low voltage", P1 VSS "Ground", P2 A5 "Address Inputs: Provide the row address for Active commands and the column address for Read/ Write commands to select one location out of the memory array in the respective bank. (A10/AP and A12/BC# have additional functions; see below). The address inpu", P3 A2 "Address Inputs: Provide the row address for Active commands and the column address for Read/ Write commands to select one location out of the memory array in the respective bank. (A10/AP and A12/BC# have additional functions; see below). The address inpu", P7 A1 "Address Inputs: Provide the row address for Active commands and the column address for Read/ Write commands to select one location out of the memory array in the respective bank. (A10/AP and A12/BC# have additional functions; see below). The address inpu", P8 A4 "Address Inputs: Provide the row address for Active commands and the column address for Read/ Write commands to select one location out of the memory array in the respective bank. (A10/AP and A12/BC# have additional functions; see below). The address inpu", P9 VSS "Ground", R1 VDD "Power Supply: 1.5 V +/- 0.075 V for standard voltage or 1.35V +0.1V, -0.067V for low voltage", R2 A7 "Address Inputs: Provide the row address for Active commands and the column address for Read/ Write commands to select one location out of the memory array in the respective bank. (A10/AP and A12/BC# have additional functions; see below). The address inpu", R3 A9 "Address Inputs: Provide the row address for Active commands and the column address for Read/ Write commands to select one location out of the memory array in the respective bank. (A10/AP and A12/BC# have additional functions; see below). The address inpu", R7 A11 "Address Inputs: Provide the row address for Active commands and the column address for Read/ Write commands to select one location out of the memory array in the respective bank. (A10/AP and A12/BC# have additional functions; see below). The address inpu", R8 A6 "Address Inputs: Provide the row address for Active commands and the column address for Read/ Write commands to select one location out of the memory array in the respective bank. (A10/AP and A12/BC# have additional functions; see below). The address inpu", R9 VDD "Power Supply: 1.5 V +/- 0.075 V for standard voltage or 1.35V +0.1V, -0.067V for low voltage", T1 VSS "Ground", T2 RESET# "Active Low Asynchronous Reset: Reset is active when RESET# is LOW, and inactive when RESET# is HIGH. RESET# must be HIGH during normal operation. RESET# is a CMOS rail- to-rail signal with DC high and low at 80% and 20% of VDD, i.e., 1.20V for DC high an", T3 A13 "Burst Chop: A12 / BC# is sampled during Read and Write commands to determine if burst chop (on-the-fly) will be performed. (HIGH, no burst chop; LOW: burst chopped). See command truth table for details.", T7 A14 "Burst Chop: A12 / BC# is sampled during Read and Write commands to determine if burst chop (on-the-fly) will be performed. (HIGH, no burst chop; LOW: burst chopped). See command truth table for details.", T8 A8 "Address Inputs: Provide the row address for Active commands and the column address for Read/ Write commands to select one location out of the memory array in the respective bank. (A10/AP and A12/BC# have additional functions; see below). The address inpu", T9 VSS "Ground"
